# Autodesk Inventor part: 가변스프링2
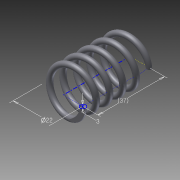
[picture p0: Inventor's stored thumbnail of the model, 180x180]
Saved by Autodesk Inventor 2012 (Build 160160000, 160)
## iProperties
Created: 2015-02
Part Number: 가변스프링2
Material: 탄소강
Document SubType Name: Modeling
Designer: Owner
Mass: 18.9178 g
Surface Area: 32.6276 cm^2
Volume: 2.40379 cm^3
Density: 7.87 g/cm^3
Author: Owner
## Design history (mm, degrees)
sketch "스케치1"
  geometry: L1 (0, 0)-(11, 0); L2 (11, 0)-(11, 40.095); L3 (11, 40.095)-(0, 40.095); L4 (0, 40.095)-(0, 0); C1 r 1.5 at (11, 0)
  constraints: 8 end point, 2 parallel, 1 centre point, 1 coincident, 1 horizontal, 1 perpendicular
  dimensions: "d0" = 22 diameter of L2 L4; "d1" = 40.0955 distance of L1.end L2.end (derived); "d2" = 3 diameter of C1
feature "코일1" pitch "d3" = 10; turns "d5" = 5; dims "d4" = 40.0955 (= d1), "d6" = 0, angle "d7" = 90 deg, angle "d8" = 90 deg, "d9" = 0, "d10" = 0
sketch "스케치2"
  geometry: L1 (-12.5, 0)-(-9.5, 0) reference; 1 further point
  constraints: 1 horizontal alignment
extrude "돌출1" cut sketch "스케치2" stored distance "d11" = 10; taper "d12" = 0 deg
node "작업 평면1"
sketch "스케치3"
  geometry: L1 (-9.5, 0)-(-12.5, 0) reference; 1 further point
  constraints: 1 horizontal alignment
extrude "돌출2" cut sketch "스케치3" stored distance "d13" = 10; taper "d14" = 0 deg
node "솔리드1"
node "절단 모서리 투영1"
node "절단 모서리 투영2"
